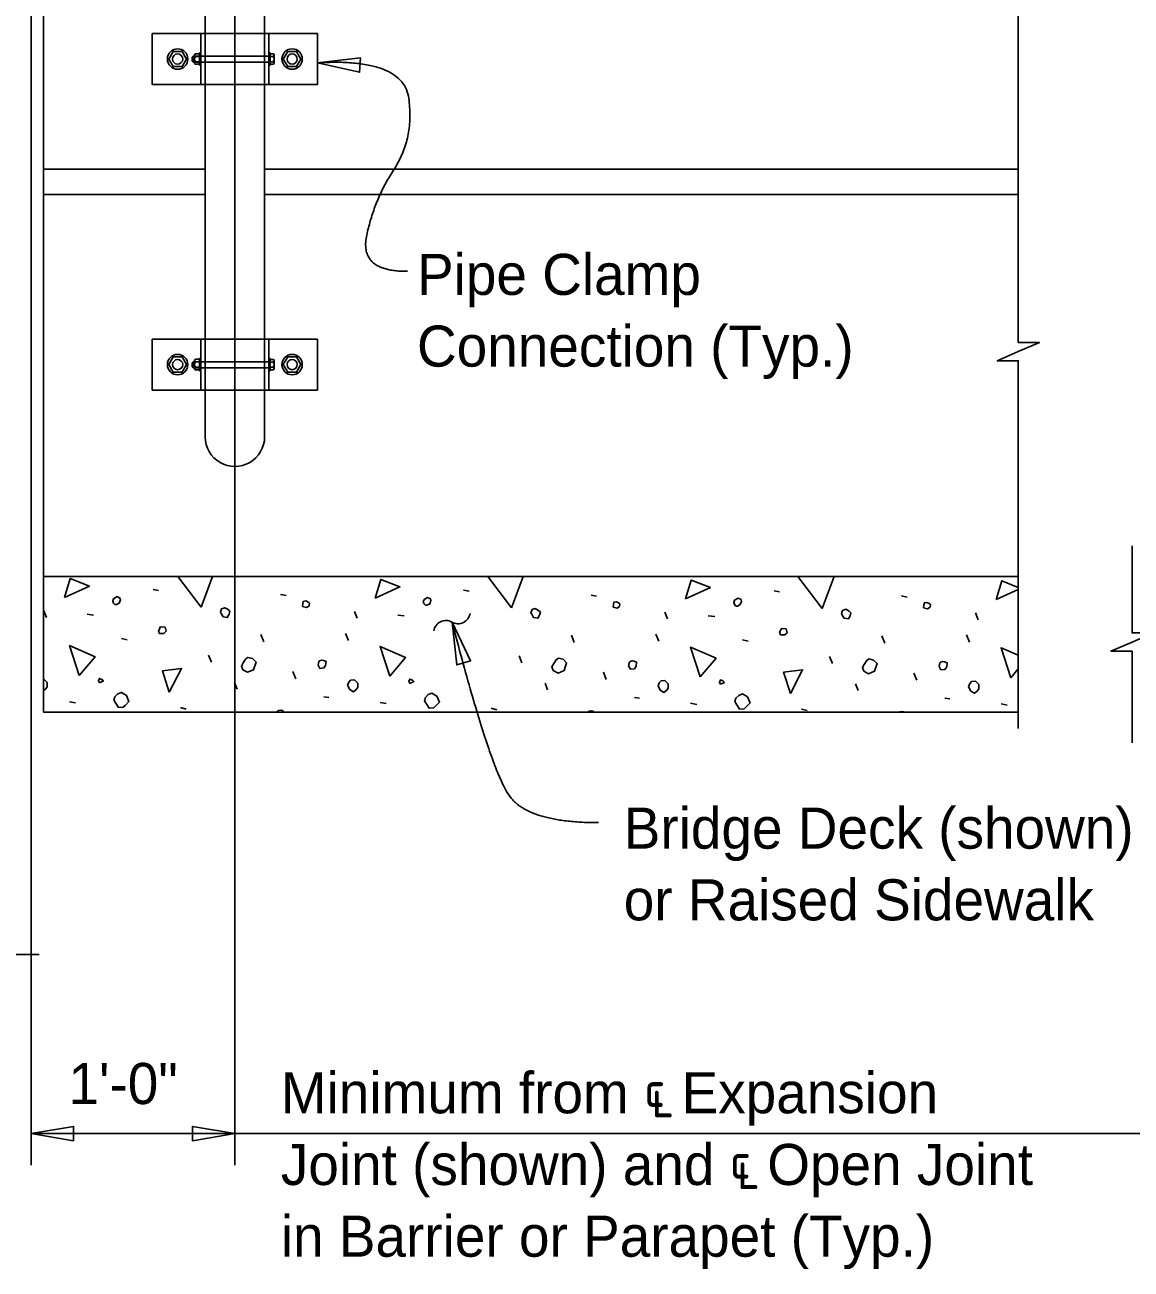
# Model space of a CAD drawing. Extents: x 0 to 41.1, y 0 to 25.9.
# Drawn here: x 23.58 to 29.01, y 10.82 to 16.93 of the extents above; entities that cross this region are included whole.
import ezdxf

# ---------------------------------------------------------------- set-up
doc = ezdxf.new("R2010")
doc.units = 0
for name, color, linetype in [('CL_Major', 7, 'Continuous'), ('Dimension', 7, 'Continuous'), ('Miscellaneous', 7, 'Continuous'), ('SteelMisc', 7, 'Continuous'), ('SteelMisc_h', 7, 'Continuous'), ('SupstrConc', 7, 'Continuous'), ('TextStructures', 7, 'Continuous')]:
    doc.layers.add(name, color=color, linetype=linetype)

msp = doc.modelspace()

# ---------------------------------------------------------------- linework, layer by layer
at = {"layer": 'CL_Major'}
for p, q in [((24.6151, 11.3358), (24.6151, 25.0052)), ((23.6151, 11.3358), (23.6151, 17.2313))]:
    msp.add_line(p, q, dxfattribs=at)
at = {"layer": 'Dimension'}
msp.add_line((23.6151, 11.4901), (29.4153, 11.4901), dxfattribs=at)
for points in [[(28.4596, 17.2246), (28.4596, 15.3737), (28.5629, 15.3737), (28.4596, 15.3287), (28.3562, 15.2837), (28.4596, 15.2837), (28.4596, 13.4788)], [(29.0176, 14.3746), (29.0176, 13.9474), (29.1209, 13.9474), (29.0176, 13.9024), (28.9142, 13.8574), (29.0176, 13.8574), (29.0176, 13.4079)], [(23.6547, 12.3699), (22.9577, 12.3699), (22.9577, 12.2536), (22.8583, 12.4786), (22.8583, 12.3699), (22.2031, 12.3699)]]:
    msp.add_lwpolyline(points, dxfattribs=at)
for points in [[(25.0211, 16.7461), (25.2271, 16.6998), (25.2309, 16.7703)], [(25.6811, 14.0008), (25.7034, 13.7907), (25.7713, 13.8098)], [(23.6151, 11.4901), (23.8234, 11.4549), (23.8234, 11.5254)], [(24.6151, 11.4902), (24.4069, 11.5255), (24.4069, 11.4549)]]:
    msp.add_lwpolyline(points, close=True, dxfattribs=at)
for centre, start, end in [((25.6504, 13.9489), 59.84335, 171.57057), ((25.7103, 14.052), 239.84335, 351.57057)]:
    msp.add_arc(centre, 0.0596, start, end, dxfattribs=at)
for points in [[(25.4627, 15.7225), (25.2257, 15.7202), (25.2971, 16.0714), (25.4956, 16.3764), (25.4402, 16.7692), (25.021, 16.7461)], [(26.3997, 13.0164), (26.0593, 13.0164), (25.8702, 13.2719), (25.6811, 14.0007)]]:
    msp.add_open_spline(points, degree=2, dxfattribs=at)
at = {"layer": 'Miscellaneous'}
for p, q in [((24.4075, 16.7575), (24.4075, 16.7696)), ((24.4132, 16.7575), (24.4132, 16.7696)), ((24.4075, 15.2575), (24.4075, 15.2696)), ((24.4132, 15.2575), (24.4132, 15.2696)), ((24.2137, 14.1609), (24.2402, 14.1556)), ((24.8395, 14.1361), (24.866, 14.1308)), ((25.7375, 14.1573), (25.7641, 14.152)), ((26.3633, 14.1326), (26.3898, 14.1273)), ((27.2613, 14.1538), (27.2879, 14.1485)), ((27.8871, 14.129), (27.9137, 14.1237)), ((23.6905, 14.023), (23.6781, 14.0566)), ((25.2143, 14.0194), (25.2019, 14.053)), ((26.7381, 14.0159), (26.7257, 14.0495)), ((23.8902, 14.0389), (23.922, 14.0353)), ((25.414, 14.0353), (25.4459, 14.0318)), ((26.9378, 14.0318), (26.9697, 14.0283)), ((28.2619, 14.0124), (28.2495, 14.046)), ((24.7564, 13.9045), (24.7423, 13.9399)), ((25.1718, 13.9098), (25.1577, 13.9452)), ((26.2802, 13.901), (26.2661, 13.9364)), ((26.6957, 13.9063), (26.6815, 13.9417)), ((27.8041, 13.8975), (27.7899, 13.9328)), ((28.2195, 13.9028), (28.2053, 13.9381)), ((24.0582, 13.9204), (24.0864, 13.9134)), ((27.1058, 13.9134), (27.1341, 13.9063)), ((24.5001, 13.8038), (24.486, 13.8391)), ((26.0239, 13.8002), (26.0098, 13.8356)), ((27.5477, 13.7967), (27.5336, 13.8321)), ((24.9138, 13.7225), (24.8996, 13.7578)), ((26.4376, 13.7189), (26.4234, 13.7543)), ((27.9614, 13.7154), (27.9472, 13.7507)), ((24.6256, 13.6712), (24.6132, 13.7048)), ((26.1494, 13.6677), (26.137, 13.7012)), ((27.6732, 13.6641), (27.6609, 13.6977)), ((25.0516, 13.6341), (25.0764, 13.6305)), ((26.5755, 13.6305), (26.6002, 13.627)), ((28.0993, 13.627), (28.124, 13.6235)), ((23.8036, 13.6093), (23.8336, 13.604)), ((24.3481, 13.581), (24.3764, 13.574)), ((25.3274, 13.6058), (25.3575, 13.6005)), ((25.8719, 13.5775), (25.9002, 13.5704)), ((26.8512, 13.6022), (26.8813, 13.5969)), ((27.3957, 13.574), (27.424, 13.5669)), ((28.375, 13.5987), (28.4051, 13.5934))]:
    msp.add_line(p, q, dxfattribs=at)
for points in [[(23.7788, 14.122), (23.8071, 14.2139), (23.9008, 14.1768), (23.7788, 14.122)], [(24.4488, 14.0742), (24.3346, 14.2245)], [(24.505, 14.2245), (24.4488, 14.0742)], [(25.3027, 14.1184), (25.3309, 14.2104), (25.4246, 14.1732), (25.3027, 14.1184)], [(25.9726, 14.0707), (25.8558, 14.2245)], [(26.0301, 14.2245), (25.9726, 14.0707)], [(26.8265, 14.1149), (26.8548, 14.2068), (26.9485, 14.1697), (26.8265, 14.1149)], [(27.4965, 14.0672), (27.3769, 14.2245)], [(27.5553, 14.2245), (27.4965, 14.0672)], [(28.3503, 14.1114), (28.3786, 14.2033), (28.4595, 14.1712)], [(24.0263, 14.0866), (24.0334, 14.0866), (24.0475, 14.0937), (24.0529, 14.1096), (24.0511, 14.1184), (24.0369, 14.1255), (24.0193, 14.1149), (24.0157, 14.1043), (24.0193, 14.0937), (24.0263, 14.0866)], [(25.5502, 14.0831), (25.5572, 14.0831), (25.5714, 14.0901), (25.5767, 14.1061), (25.5749, 14.1149), (25.5608, 14.122), (25.5431, 14.1114), (25.5395, 14.1008), (25.5431, 14.0901), (25.5502, 14.0831)], [(27.074, 14.0795), (27.081, 14.0795), (27.0952, 14.0866), (27.1005, 14.1025), (27.0987, 14.1114), (27.0846, 14.1184), (27.0669, 14.1078), (27.0634, 14.0972), (27.0669, 14.0866), (27.074, 14.0795)], [(28.4595, 14.1604), (28.3503, 14.1114)], [(24.5478, 14.0424), (24.5567, 14.0265), (24.5779, 14.023), (24.5867, 14.0389), (24.5903, 14.053), (24.5814, 14.0619), (24.5655, 14.0707), (24.5496, 14.0654), (24.5443, 14.0495), (24.5478, 14.0424)], [(24.9473, 14.0778), (24.9668, 14.0725), (24.9792, 14.0813), (24.9809, 14.0937), (24.9774, 14.0972), (24.9633, 14.1043), (24.9509, 14.1025), (24.9491, 14.0901), (24.9473, 14.0778)], [(26.0716, 14.0389), (26.0805, 14.023), (26.1017, 14.0194), (26.1105, 14.0353), (26.1141, 14.0495), (26.1052, 14.0583), (26.0893, 14.0672), (26.0734, 14.0619), (26.0681, 14.046), (26.0716, 14.0389)], [(26.4712, 14.0742), (26.4906, 14.0689), (26.503, 14.0778), (26.5047, 14.0901), (26.5012, 14.0937), (26.4871, 14.1008), (26.4747, 14.099), (26.4729, 14.0866), (26.4712, 14.0742)], [(27.5955, 14.0353), (27.6043, 14.0194), (27.6255, 14.0159), (27.6343, 14.0318), (27.6379, 14.046), (27.629, 14.0548), (27.6131, 14.0636), (27.5972, 14.0583), (27.5919, 14.0424), (27.5955, 14.0353)], [(27.995, 14.0707), (28.0144, 14.0654), (28.0268, 14.0742), (28.0286, 14.0866), (28.025, 14.0901), (28.0109, 14.0972), (27.9985, 14.0954), (27.9967, 14.0831), (27.995, 14.0707)], [(24.2455, 13.9452), (24.2668, 13.9452), (24.2774, 13.9558), (24.2721, 13.9752), (24.2491, 13.977), (24.2455, 13.9664), (24.2402, 13.9576), (24.2455, 13.9452), (24.242, 13.9487)], [(27.2932, 13.9381), (27.3144, 13.9381), (27.325, 13.9487), (27.3197, 13.9682), (27.2967, 13.9699), (27.2932, 13.9593), (27.2879, 13.9505), (27.2932, 13.9381), (27.2896, 13.9417)], [(23.8513, 13.7384), (23.8036, 13.8851), (23.9291, 13.8303), (23.8513, 13.7384)], [(25.3751, 13.7348), (25.3274, 13.8815), (25.4529, 13.8267), (25.3751, 13.7348)], [(26.899, 13.7313), (26.8512, 13.878), (26.9767, 13.8232), (26.899, 13.7313)], [(28.4228, 13.7278), (28.375, 13.8745), (28.4595, 13.8376)], [(24.6539, 13.7666), (24.6769, 13.7543), (24.7069, 13.7666), (24.7193, 13.8038), (24.7016, 13.8214), (24.6786, 13.8267), (24.668, 13.8197), (24.6557, 13.8002), (24.6468, 13.7843), (24.6539, 13.7666)], [(25.0234, 13.7896), (25.0322, 13.7737), (25.0516, 13.7755), (25.0605, 13.7879), (25.0622, 13.8073), (25.0499, 13.8126), (25.041, 13.8144), (25.0304, 13.8108), (25.0269, 13.8073), (25.0234, 13.7896)], [(26.1777, 13.7631), (26.2007, 13.7507), (26.2307, 13.7631), (26.2431, 13.8002), (26.2254, 13.8179), (26.2025, 13.8232), (26.1919, 13.8161), (26.1795, 13.7967), (26.1706, 13.7808), (26.1777, 13.7631)], [(26.5472, 13.7861), (26.556, 13.7702), (26.5755, 13.7719), (26.5843, 13.7843), (26.5861, 13.8038), (26.5737, 13.8091), (26.5648, 13.8108), (26.5542, 13.8073), (26.5507, 13.8038), (26.5472, 13.7861)], [(27.7015, 13.7596), (27.7245, 13.7472), (27.7546, 13.7596), (27.7669, 13.7967), (27.7493, 13.8144), (27.7263, 13.8197), (27.7157, 13.8126), (27.7033, 13.7932), (27.6945, 13.7773), (27.7015, 13.7596)], [(28.071, 13.7826), (28.0798, 13.7666), (28.0993, 13.7684), (28.1081, 13.7808), (28.1099, 13.8002), (28.0975, 13.8055), (28.0887, 13.8073), (28.0781, 13.8038), (28.0745, 13.8002), (28.071, 13.7826)], [(28.9269, 13.863), (28.9241, 13.8574)], [(24.2933, 13.657), (24.2597, 13.7613), (24.3534, 13.7737), (24.2933, 13.657)], [(27.3409, 13.65), (27.3073, 13.7543), (27.401, 13.7666), (27.3409, 13.65)], [(28.4595, 13.7712), (28.4228, 13.7278)], [(23.6763, 13.665), (23.6869, 13.673), (23.694, 13.6836), (23.694, 13.7048), (23.6781, 13.7207), (23.6763, 13.7205)], [(23.9503, 13.703), (23.9698, 13.7118), (23.9627, 13.7189), (23.9503, 13.7242), (23.945, 13.7118), (23.9503, 13.703)], [(25.1683, 13.6906), (25.1789, 13.6694), (25.1966, 13.6588), (25.2107, 13.6694), (25.2178, 13.68), (25.2178, 13.7012), (25.2019, 13.7171), (25.1825, 13.7154), (25.1736, 13.7065), (25.1683, 13.6906)], [(25.4741, 13.6995), (25.4936, 13.7083), (25.4865, 13.7154), (25.4741, 13.7207), (25.4688, 13.7083), (25.4741, 13.6995)], [(26.6921, 13.6871), (26.7027, 13.6659), (26.7204, 13.6553), (26.7346, 13.6659), (26.7416, 13.6765), (26.7416, 13.6977), (26.7257, 13.7136), (26.7063, 13.7118), (26.6974, 13.703), (26.6921, 13.6871)], [(26.998, 13.6959), (27.0174, 13.7048), (27.0103, 13.7118), (26.998, 13.7171), (26.9926, 13.7048), (26.998, 13.6959)], [(28.2159, 13.6836), (28.2266, 13.6623), (28.2442, 13.6517), (28.2584, 13.6623), (28.2654, 13.673), (28.2654, 13.6942), (28.2495, 13.7101), (28.2301, 13.7083), (28.2212, 13.6995), (28.2159, 13.6836)], [(24.021, 13.6182), (24.044, 13.581), (24.067, 13.5828), (24.0758, 13.5916), (24.0953, 13.6111), (24.0829, 13.6411), (24.0582, 13.6553), (24.0405, 13.6482), (24.0263, 13.6341), (24.021, 13.6182)], [(25.5448, 13.6146), (25.5678, 13.5775), (25.5908, 13.5793), (25.5996, 13.5881), (25.6191, 13.6075), (25.6067, 13.6376), (25.582, 13.6517), (25.5643, 13.6447), (25.5502, 13.6305), (25.5448, 13.6146)], [(27.0687, 13.6111), (27.0916, 13.574), (27.1146, 13.5757), (27.1235, 13.5846), (27.1429, 13.604), (27.1305, 13.6341), (27.1058, 13.6482), (27.0881, 13.6411), (27.074, 13.627), (27.0687, 13.6111)], [(24.8519, 13.5578), (24.8501, 13.5669), (24.8413, 13.5687), (24.8289, 13.5669), (24.8198, 13.5578)], [(26.375, 13.5578), (26.3739, 13.5634), (26.3651, 13.5651), (26.3527, 13.5634), (26.3472, 13.5578)], [(27.8981, 13.5578), (27.8977, 13.5598), (27.8889, 13.5616), (27.8765, 13.5598), (27.8745, 13.5578)]]:
    msp.add_lwpolyline(points, dxfattribs=at)
at = {"layer": 'SteelMisc'}
for p, q in [((24.4692, 16.8894), (24.4692, 23.2644)), ((24.7609, 16.8894), (24.7609, 23.2644)), ((24.2091, 16.8894), (25.021, 16.8894)), ((24.2091, 16.6394), (24.2091, 16.8894)), ((24.4484, 16.8894), (24.4484, 16.6394)), ((24.7817, 16.8894), (24.7817, 16.6394)), ((25.021, 16.8894), (25.021, 16.6394)), ((24.4418, 16.7947), (24.4418, 16.734)), ((24.4418, 16.7947), (24.4484, 16.7947)), ((24.788, 16.7947), (24.782, 16.7947)), ((24.788, 16.7947), (24.788, 16.734)), ((24.4047, 16.7724), (24.4103, 16.7789)), ((24.4047, 16.7547), (24.4047, 16.7724)), ((24.4047, 16.7547), (24.4103, 16.749)), ((24.4103, 16.7789), (24.4168, 16.7789)), ((24.4103, 16.749), (24.4103, 16.7789)), ((24.4103, 16.749), (24.4168, 16.749)), ((24.4168, 16.7823), (24.4168, 16.7465)), ((24.4215, 16.7774), (24.4418, 16.7774)), ((24.4215, 16.7514), (24.4418, 16.7514)), ((24.4217, 16.7904), (24.4418, 16.7904)), ((24.4218, 16.7384), (24.4418, 16.7384)), ((24.4418, 16.7904), (24.4418, 16.7384)), ((24.4418, 16.734), (24.4484, 16.734)), ((24.788, 16.734), (24.782, 16.734)), ((24.8027, 16.7903), (24.788, 16.7903)), ((24.8028, 16.7773), (24.788, 16.7773)), ((24.8028, 16.7514), (24.788, 16.7514)), ((24.8027, 16.7384), (24.788, 16.7384)), ((24.8078, 16.745), (24.8078, 16.7838)), ((25.021, 16.6394), (24.2091, 16.6394)), ((24.4692, 16.6394), (24.4692, 15.3894)), ((24.7609, 16.6394), (24.7609, 15.3894)), ((24.2091, 15.3894), (25.021, 15.3894)), ((24.2091, 15.1394), (24.2091, 15.3894)), ((24.4484, 15.3894), (24.4484, 15.1394)), ((24.7817, 15.3894), (24.7817, 15.1394)), ((25.021, 15.3894), (25.021, 15.1394)), ((24.4047, 15.2724), (24.4103, 15.2789)), ((24.4047, 15.2547), (24.4047, 15.2724)), ((24.4103, 15.2789), (24.4168, 15.2789)), ((24.4103, 15.249), (24.4103, 15.2789)), ((24.4168, 15.2823), (24.4168, 15.2465)), ((24.4215, 15.2774), (24.4418, 15.2774)), ((24.4217, 15.2904), (24.4418, 15.2904)), ((24.4418, 15.2947), (24.4418, 15.234)), ((24.4418, 15.2947), (24.4484, 15.2947)), ((24.4418, 15.2904), (24.4418, 15.2384)), ((24.788, 15.2947), (24.782, 15.2947)), ((24.788, 15.2947), (24.788, 15.234)), ((24.8027, 15.2903), (24.788, 15.2903)), ((24.8028, 15.2773), (24.788, 15.2773)), ((24.8078, 15.245), (24.8078, 15.2838)), ((24.4047, 15.2547), (24.4103, 15.249)), ((24.4103, 15.249), (24.4168, 15.249)), ((24.4215, 15.2514), (24.4418, 15.2514)), ((24.4218, 15.2384), (24.4418, 15.2384)), ((24.4418, 15.234), (24.4484, 15.234)), ((24.788, 15.234), (24.782, 15.234)), ((24.8028, 15.2514), (24.788, 15.2514)), ((24.8027, 15.2384), (24.788, 15.2384)), ((25.021, 15.1394), (24.2091, 15.1394)), ((24.4692, 15.1394), (24.4692, 14.9102)), ((24.7609, 14.9102), (24.7609, 15.1394))]:
    msp.add_line(p, q, dxfattribs=at)
for points in [[(24.3124, 16.8019), (24.3557, 16.8019), (24.3774, 16.7644), (24.3557, 16.7269), (24.3124, 16.7269), (24.2907, 16.7644)], [(24.8744, 16.8019), (24.9177, 16.8019), (24.9394, 16.7644), (24.9177, 16.7269), (24.8744, 16.7269), (24.8527, 16.7644)], [(24.3124, 15.3019), (24.3557, 15.3019), (24.3774, 15.2644), (24.3557, 15.2269), (24.3124, 15.2269), (24.2907, 15.2644)], [(24.8744, 15.3019), (24.9177, 15.3019), (24.9394, 15.2644), (24.9177, 15.2269), (24.8744, 15.2269), (24.8527, 15.2644)]]:
    msp.add_lwpolyline(points, close=True, dxfattribs=at)
for centre, radius in [((24.3341, 16.7644), 0.05), ((24.896, 16.7644), 0.05), ((24.3341, 16.7644), 0.025), ((24.896, 16.7644), 0.025), ((24.3341, 15.2644), 0.05), ((24.3341, 15.2644), 0.025), ((24.896, 15.2644), 0.05), ((24.896, 15.2644), 0.025)]:
    msp.add_circle(centre, radius, dxfattribs=at)
for centre, radius, start, end in [((24.4234, 16.7838), 0.00674, 104.48908, 254.18889), ((24.4363, 16.7644), 0.0196, 138.62797, 221.37203), ((24.4234, 16.7449), 0.00673, 105.7823, 255.54039), ((24.801, 16.7838), 0.00673, 285.7823, 75.54039), ((24.801, 16.7449), 0.00674, 284.48908, 74.18889), ((24.7881, 16.7644), 0.0196, 318.62797, 41.37203), ((24.4234, 15.2838), 0.00674, 104.48908, 254.18889), ((24.4363, 15.2644), 0.0196, 138.62797, 221.37203), ((24.801, 15.2838), 0.00673, 285.7823, 75.54039), ((24.7881, 15.2644), 0.0196, 318.62797, 41.37203), ((24.4234, 15.2449), 0.00673, 105.7823, 255.54039), ((24.801, 15.2449), 0.00674, 284.48908, 74.18889)]:
    msp.add_arc(centre, radius, start, end, dxfattribs=at)
msp.add_ellipse((24.6151, 14.9102), major_axis=(0, 0.1458), ratio=0.999499, start_param=1.570796, end_param=4.712389, dxfattribs=at)
at = {"layer": 'SteelMisc_h'}
for p, q in [((24.4692, 16.8894), (24.4692, 16.6394)), ((24.7609, 16.8894), (24.7609, 16.6394)), ((24.7817, 16.7789), (24.4168, 16.7789)), ((24.4168, 16.749), (24.7817, 16.749)), ((24.4692, 15.3894), (24.4692, 15.1394)), ((24.7609, 15.3894), (24.7609, 15.1394)), ((24.7817, 15.2789), (24.4168, 15.2789)), ((24.4168, 15.249), (24.7817, 15.249))]:
    msp.add_line(p, q, dxfattribs=at)
at = {"layer": 'SupstrConc'}
for p, q in [((23.6763, 17.2245), (23.6763, 13.5578)), ((23.6763, 16.2245), (24.4692, 16.2245)), ((24.7609, 16.2245), (28.4595, 16.2245)), ((24.7609, 16.2245), (26.002, 16.2245)), ((23.6763, 16.0995), (24.4692, 16.0995)), ((24.7609, 16.0995), (28.4596, 16.0995)), ((23.6763, 14.2245), (28.4595, 14.2245)), ((23.6763, 13.5578), (28.4595, 13.5578))]:
    msp.add_line(p, q, dxfattribs=at)

# ---------------------------------------------------------------- texts
at = {"layer": 'Dimension'}
for s, p in [('Pipe Clamp ', (25.5087, 15.6066)), ('Connection (Typ.)', (25.5087, 15.2546)), ('Bridge Deck (shown)', (26.5232, 12.8886)), ('or Raised Sidewalk', (26.5232, 12.5366)), ('Minimum from ℄ Expansion', (24.8405, 11.5897)), ('Joint (shown) and ℄ Open Joint ', (24.8405, 11.2377)), ('in Barrier or Parapet (Typ.)', (24.8405, 10.8857))]:
    msp.add_text(s, height=0.2016, dxfattribs=at).set_placement(p)
at = {"layer": 'TextStructures'}
msp.add_text('1\'-0"', height=0.2016, dxfattribs=at).set_placement((23.7982, 11.6351))

doc.saveas('drawing.dxf')
